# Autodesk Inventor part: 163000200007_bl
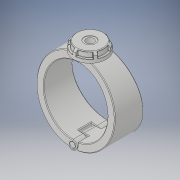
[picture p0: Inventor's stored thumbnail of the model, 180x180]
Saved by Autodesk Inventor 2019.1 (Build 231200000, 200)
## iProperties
Created: 2022-02
Part Number: 163000200007_bl
Material: Generic
Description: Plassadle Threaded 200x1 3/4''
Document SubType Name: Modeling
Designer: comp2
Density: 1 g/cm^3
Appearance: Default
Author: comp2
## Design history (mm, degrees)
derived "16300.ipt"
feature "Solid1::16300.ipt" dims "ScaleForDerivedMember" = 10
feature "Solid2::16300.ipt" dims "ScaleForDerivedMember" = 10
feature "Solid3::16300.ipt" dims "ScaleForDerivedMember" = 10
feature "Solid4::16300.ipt" dims "ScaleForDerivedMember" = 10
tag "TaggingFeature1"
body "Solid1"
body "Solid2"
body "Solid3"
body "Solid4"
other parameters: "d2" = 246 [user parameter], "d7" = 233.7 [user parameter], "d8" = 85 deg [user parameter], "d9" = 45 deg [user parameter], "d10" = 102 [user parameter], "d11" = 49 [user parameter], "d12" = 19.061 [user parameter], "d13" = 42.84 [user parameter], "d14" = 36.1755 [user parameter], "d42" = 4.6 [user parameter], "d49" = 4.92 [user parameter], "d50" = 115 [user parameter], "d51" = 0 [user parameter], "d52" = 32.2 [user parameter], "d53" = 135.3 [user parameter], "d54" = 40.25 [user parameter], "d55" = 0 [user parameter], "d56" = 23 [user parameter], "d57" = 23 [user parameter], "d59" = 0 [user parameter], "d60" = 115 [user parameter], "d61" = 0 [user parameter], "d62" = 40.25 [user parameter], "d63" = 0 [user parameter], "d65" = 0 [user parameter], "d67" = 0 [user parameter], "d69" = 0 [user parameter], "d70" = 1 [user parameter], "d71" = 110.4 [user parameter], "d72" = 0 [user parameter], "d73" = 2 [user parameter], "d78" = 86.7 [user parameter], "d79" = 5.1 [user parameter], "d80" = 60 deg [user parameter], "d81" = 5.1 [user parameter], "d84" = 0 [user parameter], "d85" = 1 [user parameter], "d87" = 360 deg [user parameter], "d122" = 49 [user parameter], "d124" = 42.80128 [user parameter], "d125" = 1.3615 [user parameter], "d127" = 272 [user parameter], "d129" = 24.117 [user parameter], "d130" = 20.49945 [user parameter], "d131" = 25.97 [user parameter], "d132" = 45 deg [user parameter], "d133" = 18.179 [user parameter], "d134" = 12.0585 [user parameter], "d136" = 0 [user parameter], "d138" = 0 [user parameter], "d1" = 25 [user parameter], "B" = 246 [user parameter], "L" = 115 [user parameter], "E_" = 54 [user parameter], "E1" = 102 [user parameter], "H1" = 272 [user parameter], "H2" = 49 [user parameter], "H3" = 78 [user parameter], "H_costum" = 49 [user parameter], "Rp" = 24.117 [user parameter], "d128" = 27.23 [user parameter]
